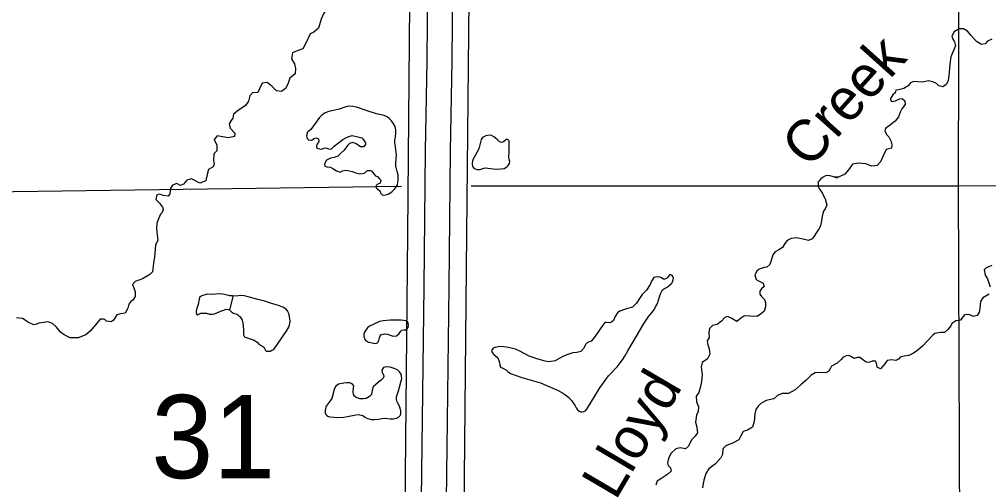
# Model space of a CAD drawing. Extents: x -492261 to -432772, y 1441225 to 1452922.
# Drawn here: x -458819.6 to -458538.4, y 1451160.3 to 1451295.2 of the extents above; entities that cross this region are included whole.
import ezdxf

# ---------------------------------------------------------------- set-up
doc = ezdxf.new("R2010")
doc.units = 0
doc.layers.add('Default', color=7, linetype='Continuous')

msp = doc.modelspace()

# ---------------------------------------------------------------- linework, layer by layer
at = {"layer": 'Default'}
for points in [[(-458775.09, 1450741.98), (-458762.55, 1450815.06), (-458753.36, 1450873.9), (-458743.23, 1450930.99), (-458732.3, 1450998.14), (-458723.97, 1451053.35), (-458714.51, 1451109.99), (-458709.23, 1451142.3), (-458708.63, 1451144.59), (-458708.2, 1451147), (-458708.04, 1451149.94), (-458707.72, 1451153.24), (-458706.96, 1451233.13), (-458706.23, 1451310.87), (-458705.47, 1451401.93), (-458705.35, 1451497.74), (-458704.15, 1451560.62), (-458704.06, 1451606.12)], [(-458757.7, 1450741.98), (-458745.63, 1450812.29), (-458736.45, 1450871.08), (-458726.32, 1450928.11), (-458715.37, 1450995.48), (-458707.04, 1451050.66), (-458697.6, 1451107.2), (-458692.45, 1451138.71), (-458691.87, 1451140.9), (-458691.14, 1451145.04), (-458690.95, 1451148.63), (-458690.58, 1451152.32), (-458689.82, 1451232.97), (-458689.08, 1451310.72), (-458688.32, 1451401.84), (-458688.21, 1451497.57), (-458687.01, 1451560.44), (-458686.91, 1451606.08)], [(-458545.7, 1451551.4), (-458546.87, 1451398.2), (-458547.27, 1451246.89), (-458546.8, 1451121.35)], [(-458741.76, 1450911.7), (-458737.69, 1450937.21), (-458734.52, 1450958.98), (-458732.41, 1450970.73), (-458726.22, 1451008.19), (-458722.62, 1451030.54), (-458717.54, 1451060.5), (-458713.99, 1451081.36), (-458709.7, 1451108.97), (-458707.85, 1451122.03), (-458704.54, 1451139.83), (-458703.02, 1451148.6), (-458702.16, 1451217.61), (-458701.82, 1451257.17), (-458701.28, 1451283.17), (-458701.01, 1451317.21), (-458701, 1451317.95)], [(-458693.86, 1451317.92), (-458693.87, 1451317.16), (-458694.14, 1451283.06), (-458694.68, 1451257.07), (-458695.02, 1451217.53), (-458695.89, 1451147.94), (-458697.51, 1451138.57), (-458700.8, 1451120.88), (-458702.63, 1451107.92), (-458706.94, 1451080.21), (-458710.5, 1451059.31), (-458715.57, 1451029.37), (-458719.17, 1451007.04), (-458725.37, 1450969.52), (-458727.47, 1450957.83), (-458730.63, 1450936.14), (-458734.7, 1450910.58)], [(-458728.63, 1451307.89), (-458729.4, 1451306.84), (-458730.19, 1451304.13), (-458730.17, 1451302.21), (-458730.27, 1451300.28), (-458730.64, 1451298.04), (-458731.35, 1451296.96), (-458732.05, 1451295.25), (-458732.85, 1451292.68), (-458734.16, 1451291.5), (-458735.26, 1451290.98), (-458736.57, 1451288.31), (-458737.38, 1451286.6), (-458739.05, 1451286.04), (-458740.41, 1451285.47), (-458740.65, 1451283.71), (-458739.79, 1451282.27), (-458739.5, 1451280.99), (-458739.63, 1451279.38), (-458741.2, 1451278.13), (-458741.73, 1451276.37), (-458742.47, 1451275.15), (-458743.59, 1451274.32), (-458745.05, 1451274.51)], [(-458537.55, 1451289.41), (-458538.77, 1451288.9), (-458539.47, 1451288.13), (-458540.52, 1451287.91), (-458541.94, 1451288.82), (-458543.53, 1451290.53), (-458544.59, 1451291.79), (-458545.7, 1451292.48), (-458546.98, 1451292.42), (-458548.45, 1451291.58), (-458549.13, 1451290.33), (-458548.79, 1451289.45), (-458548.32, 1451288.63), (-458548.09, 1451287.55), (-458548.65, 1451286.18), (-458549.41, 1451284.36), (-458549.7, 1451282.17), (-458549.86, 1451279.79), (-458550.2, 1451277.4), (-458550.72, 1451276.3), (-458551.7, 1451275.61), (-458552.88, 1451275.96), (-458553.61, 1451276.57), (-458554.66, 1451277.09), (-458555.92, 1451277.34), (-458557.51, 1451277.02), (-458558.97, 1451277.04), (-458560.21, 1451277.18), (-458561.08, 1451276.76), (-458561.78, 1451275.91), (-458563.04, 1451275.19), (-458564.63, 1451274.75), (-458565.35, 1451274.67), (-458565.56, 1451273.92), (-458566.2, 1451273.33), (-458567, 1451272.02), (-458566.58, 1451271.37), (-458565.47, 1451271.54), (-458564.28, 1451272.12), (-458563.54, 1451272.25), (-458562.75, 1451271.58), (-458562.61, 1451270.53), (-458563.64, 1451269.21), (-458564.07, 1451268.25), (-458564.61, 1451266.98), (-458565.6, 1451265.63), (-458566.95, 1451264.57), (-458568.38, 1451263.59), (-458568.57, 1451262.89), (-458568.05, 1451261.79), (-458567.43, 1451261.12), (-458566.83, 1451260.01), (-458566.55, 1451258.81), (-458566.66, 1451257.89), (-458568.2, 1451257.45), (-458569.01, 1451255.63), (-458569.85, 1451253.89), (-458570.82, 1451252.8), (-458572.31, 1451252.65), (-458574.07, 1451253.29), (-458576.19, 1451253.53), (-458577.98, 1451253.17), (-458579.14, 1451251.53), (-458580.2, 1451250.36), (-458581.95, 1451249.4), (-458583.18, 1451249.45), (-458582.29, 1451249.25), (-458584.51, 1451249.85), (-458585.11, 1451249.95), (-458585.79, 1451249.82), (-458586.47, 1451249.49), (-458587.09, 1451248.99), (-458587.61, 1451248.37), (-458587.92, 1451248.08), (-458587.91, 1451246.7), (-458587.55, 1451245.99), (-458587.14, 1451245.49), (-458586.66, 1451244.72), (-458585.97, 1451243.25), (-458585.88, 1451243.17), (-458585.38, 1451241.34), (-458585.83, 1451240.3), (-458586.33, 1451239.57), (-458586.72, 1451238.15), (-458586.89, 1451236.75), (-458587.25, 1451235.3)], [(-458745.05, 1451274.51), (-458746.34, 1451275.77), (-458747.72, 1451276.88), (-458749.23, 1451276.67), (-458749.93, 1451275.08), (-458750.47, 1451273.98), (-458752.04, 1451273.85), (-458752.74, 1451273.06), (-458753.18, 1451271.44), (-458754.04, 1451270.24), (-458756.2, 1451268.81), (-458757.52, 1451267.69), (-458757.69, 1451266.57), (-458758.16, 1451265.87), (-458758.76, 1451264.88), (-458758.44, 1451263.6), (-458757.12, 1451262.17), (-458757.24, 1451261.19), (-458759.06, 1451260.8), (-458760.67, 1451261.16), (-458762.22, 1451261.38), (-458763.14, 1451260.38), (-458762.32, 1451258.68), (-458762.31, 1451257.11), (-458763.23, 1451256.22), (-458763.33, 1451254.27), (-458763.13, 1451253.3), (-458763.39, 1451252.46), (-458764.72, 1451251.66), (-458765.11, 1451250.18), (-458765.55, 1451248.4), (-458767.25, 1451247.69), (-458769.33, 1451248.73), (-458769.71, 1451248.92), (-458771.07, 1451248.57), (-458772.02, 1451247.43), (-458772.92, 1451247.01), (-458773.91, 1451247.59), (-458775.18, 1451247.15), (-458775.82, 1451246.28), (-458776.01, 1451244.58), (-458776.45, 1451243.91), (-458777.88, 1451244.1), (-458778.86, 1451244.48), (-458779.72, 1451244.32), (-458780, 1451242.99), (-458779.02, 1451241.87), (-458778.14, 1451240.74), (-458777.92, 1451240.03), (-458778.18, 1451239.19), (-458778.72, 1451238.69), (-458779.31, 1451237.33), (-458779.74, 1451236.09), (-458779.81, 1451234.56), (-458779.7, 1451232.62), (-458779.47, 1451231.13), (-458780.15, 1451229.74), (-458780.26, 1451228.5), (-458780.46, 1451226.32), (-458780.7, 1451224.51), (-458781.04, 1451222.03), (-458781.76, 1451221.27), (-458783.96, 1451220.01), (-458786.05, 1451219.21), (-458786.8, 1451218.28), (-458786.37, 1451217.11), (-458786.03, 1451216.17), (-458786.06, 1451214.82), (-458786.72, 1451213.8), (-458787.25, 1451213.42), (-458787.89, 1451212.66), (-458788.2, 1451211.5), (-458788.97, 1451209.99), (-458790.16, 1451209.85), (-458791.36, 1451209.56), (-458792.35, 1451208.02), (-458793.05, 1451207.54), (-458794.37, 1451207.65), (-458794.84, 1451208.13), (-458795.18, 1451208.26), (-458796.24, 1451208.29), (-458797.52, 1451206.68), (-458799.07, 1451204.84), (-458800.39, 1451203.69), (-458802.57, 1451202.86), (-458804.94, 1451202.88), (-458806.68, 1451203.73), (-458807.67, 1451204.54), (-458808.91, 1451205.97), (-458810, 1451207), (-458811.38, 1451207.51), (-458813.94, 1451207.11), (-458814.65, 1451206.8), (-458815.45, 1451206.64), (-458817.21, 1451207.37), (-458817.71, 1451207.82), (-458818.73, 1451208.45), (-458820.5, 1451208.63)], [(-458713.58, 1451267.24), (-458713.83, 1451267.34), (-458716.07, 1451267.85), (-458718.72, 1451268.71), (-458721.86, 1451269.72), (-458722.9, 1451269.92), (-458724.22, 1451270), (-458724.93, 1451269.79), (-458726.83, 1451269.19), (-458728.5, 1451268.78), (-458729.9, 1451268.49), (-458731.14, 1451267.97), (-458732.12, 1451267.2), (-458732.6, 1451266.73), (-458735.11, 1451263.28), (-458736.01, 1451262.48), (-458736.32, 1451261.42), (-458736.13, 1451260.65), (-458735.75, 1451260.28), (-458734.86, 1451260.19), (-458734.1, 1451260.61), (-458733.59, 1451260.82), (-458732.87, 1451260.56), (-458732.79, 1451259.75), (-458733.26, 1451258.97), (-458733.47, 1451258.48), (-458733.43, 1451257.93), (-458733.06, 1451257.74), (-458732.42, 1451257.61), (-458731.91, 1451257.57), (-458731.26, 1451257.81), (-458730.72, 1451257.91), (-458729.91, 1451257.7), (-458729.16, 1451257.55), (-458728.27, 1451258.4), (-458725.83, 1451260.39), (-458724.9, 1451260.87), (-458724.05, 1451261.26), (-458723.06, 1451261.49), (-458721.42, 1451261.16), (-458720.29, 1451260.84), (-458719.79, 1451260.28), (-458719.26, 1451259.43), (-458719.24, 1451258.92), (-458719.77, 1451258.24), (-458720.66, 1451258.25), (-458721.33, 1451258.72), (-458721.88, 1451259.14), (-458722.86, 1451259.48), (-458723.89, 1451259.23), (-458724.3, 1451258.73), (-458725.55, 1451257.21), (-458726.39, 1451256.36), (-458727.25, 1451255.53), (-458728.27, 1451255.19), (-458729.41, 1451254.99), (-458730.51, 1451254.36), (-458730.95, 1451253.69), (-458731.08, 1451253.06), (-458730.98, 1451252.66), (-458730.41, 1451252.47), (-458729.37, 1451252.38), (-458728.68, 1451252), (-458727.66, 1451251.31), (-458726.59, 1451250.88), (-458725.89, 1451251.32), (-458724.83, 1451251.44), (-458723.13, 1451251.08), (-458721.98, 1451250.73), (-458720.83, 1451250.45), (-458719.55, 1451250.59), (-458718.93, 1451251.15), (-458718.51, 1451251.39), (-458717.79, 1451251.41), (-458717.36, 1451251.16), (-458716.91, 1451250.46), (-458716.27, 1451249.81), (-458715.66, 1451249.51), (-458715.22, 1451249.09), (-458714.8, 1451248.53), (-458714.93, 1451247.72), (-458715.83, 1451247.27), (-458716.11, 1451247.04), (-458716.12, 1451246.38), (-458715.1, 1451245.45), (-458714.95, 1451245.37), (-458714.85, 1451244.8), (-458714.27, 1451244.24), (-458713.44, 1451244.29), (-458712.62, 1451244.54)], [(-458712.62, 1451244.54), (-458711.55, 1451245.23), (-458710.93, 1451245.85), (-458710.41, 1451246.49), (-458709.97, 1451247.22), (-458709.79, 1451247.97), (-458709.74, 1451248.54), (-458709.73, 1451249.2), (-458709.75, 1451250.09), (-458710.04, 1451251.06), (-458710.39, 1451252.63), (-458710.42, 1451253.63), (-458710.19, 1451255.96), (-458710.42, 1451257.33), (-458710.56, 1451258.27), (-458710.68, 1451259.41), (-458710.7, 1451260.22), (-458710.52, 1451261.08), (-458710.44, 1451262.32), (-458710.43, 1451263.21), (-458710.6, 1451264.12), (-458711.17, 1451265.14), (-458711.64, 1451265.79), (-458712.4, 1451266.48), (-458712.93, 1451266.9), (-458713.58, 1451267.24)], [(-458677.76, 1451260.18), (-458677.87, 1451260.29), (-458677.97, 1451260.35), (-458678.16, 1451260.4), (-458678.32, 1451260.4), (-458679.21, 1451259.66), (-458679.78, 1451259.5), (-458680.36, 1451259.66), (-458680.97, 1451260.27), (-458681.59, 1451260.86), (-458681.94, 1451261.17), (-458682.69, 1451261.49), (-458683.32, 1451261.59), (-458684.32, 1451261.42), (-458685.25, 1451260.94), (-458685.7, 1451260.39), (-458685.95, 1451259.18), (-458686.37, 1451257.65), (-458688.17, 1451254.27), (-458688.29, 1451253.35), (-458688.18, 1451252.5), (-458687.66, 1451251.99), (-458686.79, 1451251.64), (-458685.93, 1451251.69), (-458685.2, 1451252), (-458684.46, 1451252.16), (-458682.96, 1451251.91), (-458682.19, 1451251.84), (-458681.3, 1451251.78), (-458680.02, 1451251.84), (-458679.02, 1451251.92), (-458678.2, 1451252.4), (-458677.84, 1451252.84), (-458677.62, 1451253.07), (-458677.48, 1451253.45), (-458677.35, 1451254.03), (-458677.51, 1451254.65), (-458677.64, 1451255.22), (-458677.68, 1451255.6), (-458677.56, 1451256.43), (-458677.58, 1451257.15), (-458677.52, 1451259.21), (-458677.53, 1451259.87), (-458677.64, 1451260.04), (-458677.76, 1451260.18)], [(-458688.57, 1451246.95), (-458547.27, 1451246.89), (-458397.09, 1451248.13), (-458246.91, 1451249.54), (-458098.46, 1451251.61), (-457946.97, 1451253.15)], [(-458842.56, 1451244.96), (-458708.77, 1451246.82)], [(-458587.25, 1451235.3), (-458587.83, 1451234.31), (-458588.35, 1451233.44), (-458589.01, 1451232.31), (-458589.67, 1451231.52), (-458590.69, 1451231.12), (-458592.27, 1451231.51), (-458594.29, 1451231.86), (-458595.74, 1451231.68), (-458596.84, 1451231.11), (-458597.59, 1451230.17), (-458598.25, 1451229.04), (-458599.34, 1451228.35), (-458600.36, 1451227.78), (-458601.08, 1451226.9), (-458601.5, 1451225.29), (-458601.87, 1451224.13), (-458602.76, 1451223.36), (-458603.53, 1451223.23), (-458604.98, 1451222.79), (-458605.68, 1451222.17), (-458606.31, 1451221.12), (-458605.88, 1451219.81), (-458605.21, 1451219.4), (-458603.82, 1451218.75), (-458603.59, 1451217.78), (-458604.32, 1451217.1), (-458604.84, 1451216.37), (-458604.82, 1451215.48), (-458604.29, 1451214.81), (-458603.5, 1451214), (-458603.13, 1451213.12), (-458603.19, 1451211.88), (-458603.52, 1451210.58), (-458604.34, 1451209.9), (-458605.6, 1451209.01), (-458607.63, 1451209.16), (-458609.29, 1451209.21), (-458610.45, 1451208.43), (-458611.48, 1451207.63), (-458613.14, 1451208.57), (-458614.15, 1451209), (-458615, 1451208.75), (-458615.95, 1451207.66), (-458617.21, 1451206.77), (-458618.52, 1451206.43), (-458619.38, 1451205.57), (-458619.58, 1451204.31), (-458619.54, 1451202.96), (-458620.06, 1451201.97), (-458619.95, 1451200.83), (-458619.52, 1451199.66), (-458619.34, 1451198.15), (-458620.04, 1451196.75), (-458621.51, 1451195.71), (-458621.84, 1451194.36), (-458621.59, 1451192.24), (-458621.77, 1451190.23), (-458621.99, 1451188.73), (-458622.51, 1451187.06), (-458623.31, 1451185.92), (-458623.22, 1451184.29), (-458622.64, 1451182.95), (-458622.72, 1451181.49), (-458623.2, 1451180.42), (-458623.49, 1451178.37), (-458623.06, 1451177.01), (-458622.9, 1451175.35), (-458623.59, 1451174.33), (-458624.62, 1451173.27), (-458625.55, 1451171.5), (-458626.39, 1451170.7), (-458627.97, 1451170.95), (-458629.19, 1451170.72), (-458630.61, 1451169.36), (-458631.32, 1451167.85), (-458631.6, 1451166.64), (-458631.38, 1451165.82), (-458630.71, 1451165.2), (-458630.57, 1451164.23), (-458631.46, 1451163.32), (-458633.29, 1451162.21), (-458634.59, 1451161.32), (-458635.01, 1451160.11)], [(-458537.49, 1451223.84), (-458539.18, 1451223.16), (-458539.71, 1451222.6), (-458539.45, 1451221.06), (-458538.76, 1451219.96), (-458538.04, 1451217.69)], [(-458673.87, 1451191.34), (-458668.48, 1451189.79), (-458666.89, 1451189.11), (-458663.54, 1451187.7), (-458662.24, 1451187.02), (-458661.1, 1451186.27), (-458660.22, 1451185.52), (-458659.46, 1451184.73), (-458658.42, 1451183.15), (-458658.06, 1451182.53), (-458657.73, 1451182), (-458657.26, 1451181.58), (-458656.86, 1451181.41), (-458656.4, 1451181.4), (-458655.92, 1451181.47), (-458655.41, 1451181.68), (-458654.96, 1451182.18), (-458651.2, 1451188.41), (-458648.72, 1451191.85), (-458646.24, 1451194.5), (-458644.63, 1451196.51), (-458643.97, 1451197.59), (-458643.15, 1451199.1), (-458640.33, 1451203.85), (-458638.52, 1451206.82), (-458637.03, 1451209.15), (-458636.34, 1451209.91), (-458635.92, 1451210.44), (-458635.4, 1451211.22), (-458635.07, 1451211.83), (-458634.55, 1451212.85), (-458633.92, 1451214.76), (-458633.49, 1451215.86), (-458633.05, 1451216.76), (-458632.49, 1451217.18), (-458631.93, 1451217.5), (-458631.33, 1451217.86), (-458631, 1451218.13), (-458630.38, 1451218.75), (-458630.17, 1451219.1), (-458629.98, 1451219.65), (-458629.91, 1451220.19), (-458630.03, 1451220.62), (-458630.21, 1451220.93), (-458630.62, 1451221.15), (-458630.99, 1451221.17), (-458631.24, 1451220.82), (-458631.63, 1451220.32), (-458631.88, 1451220.09), (-458632.33, 1451219.85), (-458632.76, 1451219.86), (-458633.51, 1451220.33), (-458634.15, 1451220.58), (-458635.09, 1451220.49), (-458635.6, 1451220.31), (-458636.26, 1451219.29), (-458636.61, 1451218.28), (-458637.71, 1451216.64), (-458638.94, 1451215.38), (-458639.74, 1451214.3), (-458640.56, 1451212.9), (-458641.73, 1451211.78), (-458643.18, 1451211.35), (-458644.06, 1451211.1), (-458645.39, 1451210.63), (-458646.15, 1451210.1), (-458646.78, 1451209.02), (-458647.27, 1451207.92), (-458647.85, 1451207.36), (-458648.37, 1451207.26), (-458649.4, 1451207.29), (-458649.77, 1451207.28), (-458650.41, 1451206.49), (-458650.85, 1451205.88), (-458651.81, 1451204.45), (-458653.16, 1451202.53), (-458653.78, 1451201.91), (-458654.77, 1451201.51), (-458655.3, 1451201.07), (-458655.98, 1451199.76), (-458656.79, 1451198.94), (-458657.87, 1451198.62), (-458659.1, 1451198.51), (-458660.83, 1451197.95), (-458662.13, 1451197.37), (-458664.18, 1451196.17), (-458666.07, 1451195.95), (-458667.1, 1451196.07), (-458669.55, 1451196.73), (-458670.59, 1451197.13)], [(-458745.78, 1451199.51), (-458742, 1451205.02), (-458741.5, 1451205.95), (-458741.24, 1451206.59), (-458741.19, 1451207.05), (-458741.12, 1451207.65), (-458741.17, 1451208.43), (-458741.34, 1451209.43), (-458741.37, 1451209.77), (-458741.83, 1451210.7), (-458742.27, 1451211.18), (-458743.2, 1451211.73), (-458744.15, 1451212.11), (-458747.03, 1451213.01), (-458748.47, 1451213.46), (-458750.46, 1451213.96), (-458753.28, 1451214.78), (-458754.46, 1451215.06), (-458755.58, 1451215.09), (-458756.63, 1451214.98), (-458757.78, 1451215.01), (-458758.55, 1451215.05), (-458759.21, 1451215.2), (-458759.76, 1451215.36), (-458760.62, 1451215.57), (-458761.68, 1451215.63), (-458763.91, 1451215.46), (-458765.03, 1451215.52), (-458766.16, 1451215.26), (-458766.7, 1451215.02), (-458767.24, 1451214.75), (-458767.45, 1451214.11), (-458767.78, 1451212.52), (-458768.23, 1451211.11), (-458768.36, 1451210.5), (-458768.32, 1451210.16), (-458768.29, 1451209.93), (-458768.23, 1451209.73), (-458768.05, 1451209.56), (-458767.99, 1451209.54), (-458766.97, 1451209.99), (-458766.29, 1451210.01), (-458765.63, 1451210), (-458765.32, 1451209.98), (-458764.45, 1451209.77), (-458763.68, 1451209.73), (-458763, 1451209.83), (-458762.32, 1451210.11), (-458760.67, 1451210.75), (-458760.33, 1451210.93), (-458759.94, 1451211.09), (-458759.28, 1451211.13), (-458758.76, 1451210.97), (-458758.71, 1451211), (-458758.09, 1451210.39), (-458757.48, 1451210.03), (-458756.79, 1451209.79), (-458756.3, 1451209.57), (-458755.62, 1451208.93), (-458755.03, 1451208.02), (-458754.81, 1451207.2), (-458754.64, 1451205.17), (-458754.65, 1451204.45), (-458754.63, 1451203.7), (-458754.3, 1451203.2), (-458753.81, 1451202.92), (-458752.98, 1451202.71), (-458752.11, 1451202.36), (-458751.5, 1451202.15), (-458750.66, 1451201.65), (-458750.13, 1451200.98), (-458749.26, 1451200.51), (-458748.74, 1451200.15), (-458748.2, 1451199.16), (-458748.02, 1451199.02), (-458747.39, 1451199.01), (-458746.91, 1451199.02), (-458746.37, 1451199.24), (-458745.78, 1451199.51)], [(-458757.72, 1451214.87), (-458758.65, 1451210.92)], [(-458540.82, 1451213.4), (-458541, 1451211.39), (-458541.17, 1451210.35), (-458541.81, 1451209.33), (-458542.97, 1451209.08), (-458544.07, 1451209.65), (-458545.44, 1451209.56), (-458546.22, 1451208.56), (-458546.63, 1451208.01), (-458547.94, 1451207.75), (-458549.07, 1451207.06), (-458549.45, 1451206.39), (-458550.23, 1451205.28), (-458551.26, 1451204.42), (-458552.4, 1451204.4), (-458554, 1451204.1), (-458554.64, 1451203.62), (-458556.15, 1451202.01), (-458557.57, 1451200.57), (-458559.02, 1451199.24), (-458560.26, 1451198.41), (-458561.62, 1451197.77), (-458562.93, 1451197.54), (-458564.06, 1451197.28), (-458564.59, 1451196.67), (-458565.41, 1451196.27), (-458566.59, 1451196.45), (-458567.87, 1451196.27), (-458568.56, 1451195.28), (-458569.81, 1451193.87), (-458570.77, 1451194.36), (-458570.97, 1451195.48), (-458571.3, 1451196.1), (-458572.27, 1451196.1), (-458573.23, 1451195.76), (-458573.98, 1451195.83), (-458575.03, 1451196.61), (-458575.76, 1451197.19), (-458576.53, 1451197.17), (-458577.44, 1451196.86), (-458578.45, 1451197.41), (-458579, 1451197.71), (-458579.77, 1451197.67), (-458580.73, 1451197.18), (-458581.18, 1451196.6), (-458582.41, 1451195.54), (-458584.04, 1451194.61), (-458584.31, 1451194.08), (-458584.84, 1451193.18), (-458585.65, 1451192.76), (-458587.37, 1451192.83), (-458588.77, 1451192.74), (-458589.92, 1451192.02), (-458591.49, 1451190.46), (-458592.72, 1451189.4), (-458594.59, 1451187.75), (-458596.48, 1451186.76), (-458598.31, 1451186.74), (-458599.67, 1451186.13), (-458600.79, 1451185.22), (-458602.95, 1451184.65), (-458604.53, 1451183.83), (-458605.28, 1451183.04), (-458605.97, 1451182.1), (-458606.31, 1451180.83), (-458606.46, 1451178.59), (-458606.99, 1451177), (-458608.42, 1451176.14), (-458609.64, 1451175.68), (-458610.43, 1451174.25), (-458610.93, 1451173.32), (-458612.53, 1451172.39), (-458614.71, 1451171.56), (-458615.52, 1451170.68), (-458615.68, 1451169.07), (-458616.14, 1451168.03), (-458617.67, 1451166.33), (-458619.58, 1451164.85), (-458620.51, 1451163.51), (-458620.96, 1451161.89), (-458621.06, 1451161.57), (-458621.21, 1451160.65), (-458621.41, 1451159.35)], [(-458538.33, 1451215.56), (-458540.08, 1451214.48), (-458540.82, 1451213.4)], [(-458708.9, 1451208.02), (-458712.1, 1451207.94), (-458714.07, 1451207.84), (-458715.18, 1451207.64), (-458717.02, 1451206.76), (-458718.03, 1451206.28), (-458718.65, 1451205.77), (-458719.15, 1451205.13), (-458719.53, 1451204.55), (-458719.72, 1451203.97), (-458719.71, 1451203.42), (-458719.61, 1451202.97), (-458719.46, 1451202.54), (-458719.25, 1451202.2), (-458718.35, 1451201.65), (-458717.65, 1451201.47), (-458716.85, 1451201.32), (-458716.25, 1451201.22), (-458715.65, 1451201.55), (-458715.35, 1451202.07), (-458715.12, 1451202.82), (-458714.99, 1451203.43), (-458714.74, 1451203.78), (-458713.75, 1451204.06), (-458712.86, 1451203.91), (-458711.5, 1451203.43), (-458711.04, 1451203.3), (-458710.18, 1451203.46), (-458709.43, 1451204.11), (-458708.96, 1451204.84), (-458708.68, 1451205.13), (-458708.14, 1451205.17), (-458707.51, 1451205.19), (-458707.15, 1451205.51), (-458706.84, 1451205.87), (-458706.74, 1451206.47), (-458706.82, 1451207.19), (-458707.03, 1451207.58), (-458707.46, 1451207.77), (-458708.9, 1451208.02)], [(-458670.59, 1451197.13), (-458671.71, 1451197.53), (-458674.47, 1451199.04), (-458675.68, 1451199.56), (-458676.55, 1451199.79), (-458677.72, 1451200.02), (-458679.1, 1451200.25), (-458680.22, 1451200.33), (-458681.59, 1451200.1), (-458682.15, 1451199.83), (-458682.62, 1451199.21), (-458682.46, 1451198.59), (-458682.02, 1451198.02), (-458680.85, 1451197.08), (-458680.45, 1451196), (-458680.26, 1451195.08), (-458680.07, 1451194.4), (-458679.4, 1451194.07), (-458678.33, 1451193.5), (-458677.89, 1451193.11), (-458677.13, 1451192.5), (-458673.87, 1451191.34)], [(-458709.6, 1451187.49), (-458708.64, 1451191.09), (-458708.84, 1451192.35), (-458709.34, 1451193.03), (-458709.96, 1451193.55), (-458710.86, 1451194.02), (-458712.07, 1451194.39), (-458713.21, 1451194.48), (-458713.98, 1451194.23), (-458714.45, 1451193.47), (-458714.43, 1451192.78), (-458713.98, 1451192.16), (-458713.86, 1451191.68), (-458714.1, 1451191.19), (-458714.63, 1451190.57), (-458715.42, 1451190.04), (-458716.26, 1451189.33), (-458716.95, 1451188.65), (-458717.24, 1451187.67), (-458717.44, 1451186.46), (-458718.03, 1451185.81), (-458719.07, 1451185.27), (-458719.84, 1451185.14), (-458720.75, 1451185.14), (-458721.91, 1451185.54), (-458722.41, 1451185.99), (-458722.68, 1451186.47), (-458722.78, 1451187.33), (-458722.67, 1451188.36), (-458722.62, 1451188.91), (-458723.07, 1451189.5), (-458723.76, 1451189.77), (-458724.59, 1451189.81), (-458725.53, 1451189.7), (-458727.01, 1451189.43), (-458727.91, 1451188.72), (-458728.32, 1451187.85), (-458729.02, 1451185.28), (-458729.77, 1451184.2), (-458730.6, 1451183.06), (-458730.7, 1451182.8), (-458730.88, 1451181.77), (-458730.89, 1451181.08), (-458730.74, 1451180.68), (-458730.47, 1451180.34), (-458729.95, 1451180.1), (-458729.43, 1451180), (-458728.4, 1451179.88), (-458727.22, 1451179.76), (-458725.54, 1451179.89), (-458724.4, 1451180.06), (-458722.01, 1451180.52), (-458721.21, 1451180.6), (-458720.03, 1451180.37), (-458719.48, 1451179.98), (-458718.84, 1451179.57), (-458717.6, 1451179.2), (-458716.57, 1451179.14), (-458715.31, 1451179.29), (-458714.49, 1451179.51), (-458713.29, 1451179.59), (-458712.06, 1451179.39), (-458711.2, 1451179.36), (-458710.23, 1451179.61), (-458709.64, 1451179.91), (-458709.33, 1451180.15), (-458709.02, 1451180.44), (-458708.92, 1451180.96), (-458708.94, 1451181.62), (-458709.13, 1451182.48), (-458709.47, 1451183.22), (-458709.83, 1451183.89), (-458710.1, 1451184.55), (-458710.2, 1451185.03), (-458710.22, 1451185.72), (-458709.98, 1451186.61), (-458709.6, 1451187.49)]]:
    msp.add_lwpolyline(points, dxfattribs=at)

# ---------------------------------------------------------------- texts
for s, rotation, p in [('Creek', 48.1299, (-458590.47, 1451251.6)), ('Lloyd', 59.5317, (-458646.67, 1451155.47))]:
    msp.add_text(s, height=12.069, rotation=rotation, dxfattribs=at).set_placement(p)
msp.add_text('31', height=24.137, dxfattribs=at).set_placement((-458781.36, 1451162.17))

doc.saveas('drawing.dxf')
